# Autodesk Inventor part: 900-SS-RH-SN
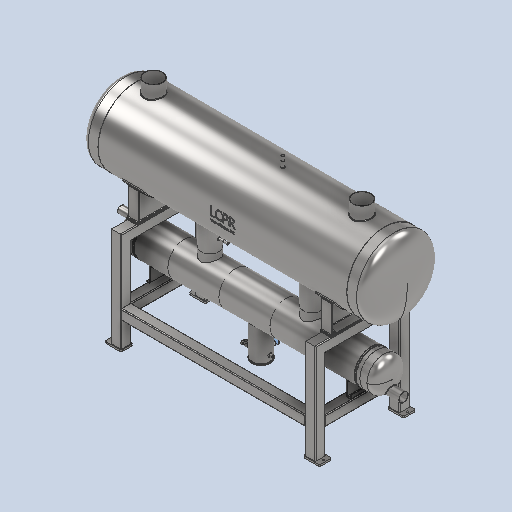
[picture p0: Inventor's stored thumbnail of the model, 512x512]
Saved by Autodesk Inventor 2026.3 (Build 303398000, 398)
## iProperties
Created: 2026-05
Part Number: 900-SS-RH-SN
Material: Generic
Document SubType Name: Modeling
Designer: rva
Density: 1 g/cm^3
Appearance: Default
Author: rva
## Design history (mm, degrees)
derived "LCPR-SS-900-RH-SN.iam"
body "Solid1"
node "Sub-SS-400-200-2646-200-100-75-RH.iam:1::LCPR-SS-400 mm Subc"
node "Sub-SS-400-200-2646-200-100-75-RH.iam:1::LCPR-SS-400 mm Subc"
node "Sub-SS-400-200-2646-200-100-75-RH.iam:1::H1100-R.ipt:2"
node "Sub-SS-400-200-2646-200-100-75-RH.iam:1::1-2 Inch NPT Socket"
node "Sub-SS-400-200-2646-200-100-75-RH.iam:1::Welds"
node "LPR-900-Frame Assembly.iam:1::LCPR-SS-Frame FOOT PLATE 195 x"
node "LPR-900-Frame Assembly.iam:1::LCPR-SS-Frame FOOT PLATE 195 x"
node "LPR-900-Frame Assembly.iam:1::LCPR-SS-Frame FOOT PLATE 195 x"
node "LPR-900-Frame Assembly.iam:1::LCPR-SS-Frame FOOT PLATE 195 x"
node "Nylon Heat Tranfer Spacer 760x125.ipt:1"
node "Nylon Heat Tranfer Spacer 760x125.ipt:2"
node "AS 1111 - Metric M16 x 160:1"
node "AS 1112 (4) - Metric M16:1"
node "AS 1237 (4.2) 16 mm:1"
node "AS 1237 (4.2) 16 mm:2"
node "AS 1111 - Metric M16 x 160:2"
node "AS 1112 (4) - Metric M16:2"
node "AS 1237 (4.2) 16 mm:3"
node "AS 1237 (4.2) 16 mm:4"
node "AS 1111 - Metric M16 x 160:3"
node "AS 1112 (4) - Metric M16:3"
node "AS 1237 (4.2) 16 mm:5"
node "AS 1237 (4.2) 16 mm:6"
node "AS 1111 - Metric M16 x 160:4"
node "AS 1112 (4) - Metric M16:4"
node "AS 1237 (4.2) 16 mm:7"
node "AS 1237 (4.2) 16 mm:8"
node "LCPR-SS-900-3000-200-SN-WELD.iam:1::900 mm LOGO.iam:1::LCPR-"
node "LCPR-SS-900-3000-200-SN-WELD.iam:1::H1100-R.ipt:1"
node "LCPR-SS-900-3000-200-SN-WELD.iam:1::LCPR-SS-900-Leg Assembly"
node "LCPR-SS-900-3000-200-SN-WELD.iam:1::900 mm-SS-Dome End Cap.i"
node "LCPR-SS-900-3000-200-SN-WELD.iam:1::LCPR-SS-900-Leg Assembly"
node "LCPR-SS-900-3000-200-SN-WELD.iam:1::900 mm-SS-Dome End Cap.i"
node "LCPR-SS-900-3000-200-SN-WELD.iam:1::Welds"
node "LCPR-SS-900-RH-SN.iam_Bodies"
